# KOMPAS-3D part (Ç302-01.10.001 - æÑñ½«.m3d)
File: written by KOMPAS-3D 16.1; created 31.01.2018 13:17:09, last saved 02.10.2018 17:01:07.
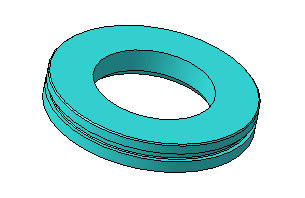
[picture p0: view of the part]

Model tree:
1. Эскиз:1
2. Операция вращения:1
     Угол 1 = 360
3. Скругление:1
     Радиус = 0.4
4. Фаска:1  (labels: Фторопласт-4  ГОСТ 10007-80 Е)
     Угол = 45; Длина 1 = 0.5; Длина 2 = 0.5

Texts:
  Линейный размер с обрывом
